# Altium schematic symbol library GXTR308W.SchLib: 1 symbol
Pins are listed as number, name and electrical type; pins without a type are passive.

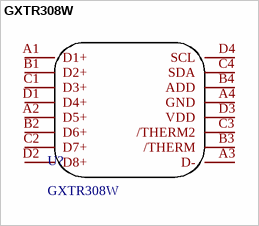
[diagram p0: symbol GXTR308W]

## GXTR308W
designator U?
footprint WLCSP-16_L1.6-W1.6-R4-C4-P0.40-TL
pins: A1 D1+, A2 D5+, A3 D-, A4 GND, B1 D2+, B2 D6+, B3 /THERM, B4 ADD, C1 D3+, C2 D7+, C3 /THERM2, C4 SDA, D1 D4+, D2 D8+, D3 VDD, D4 SCL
